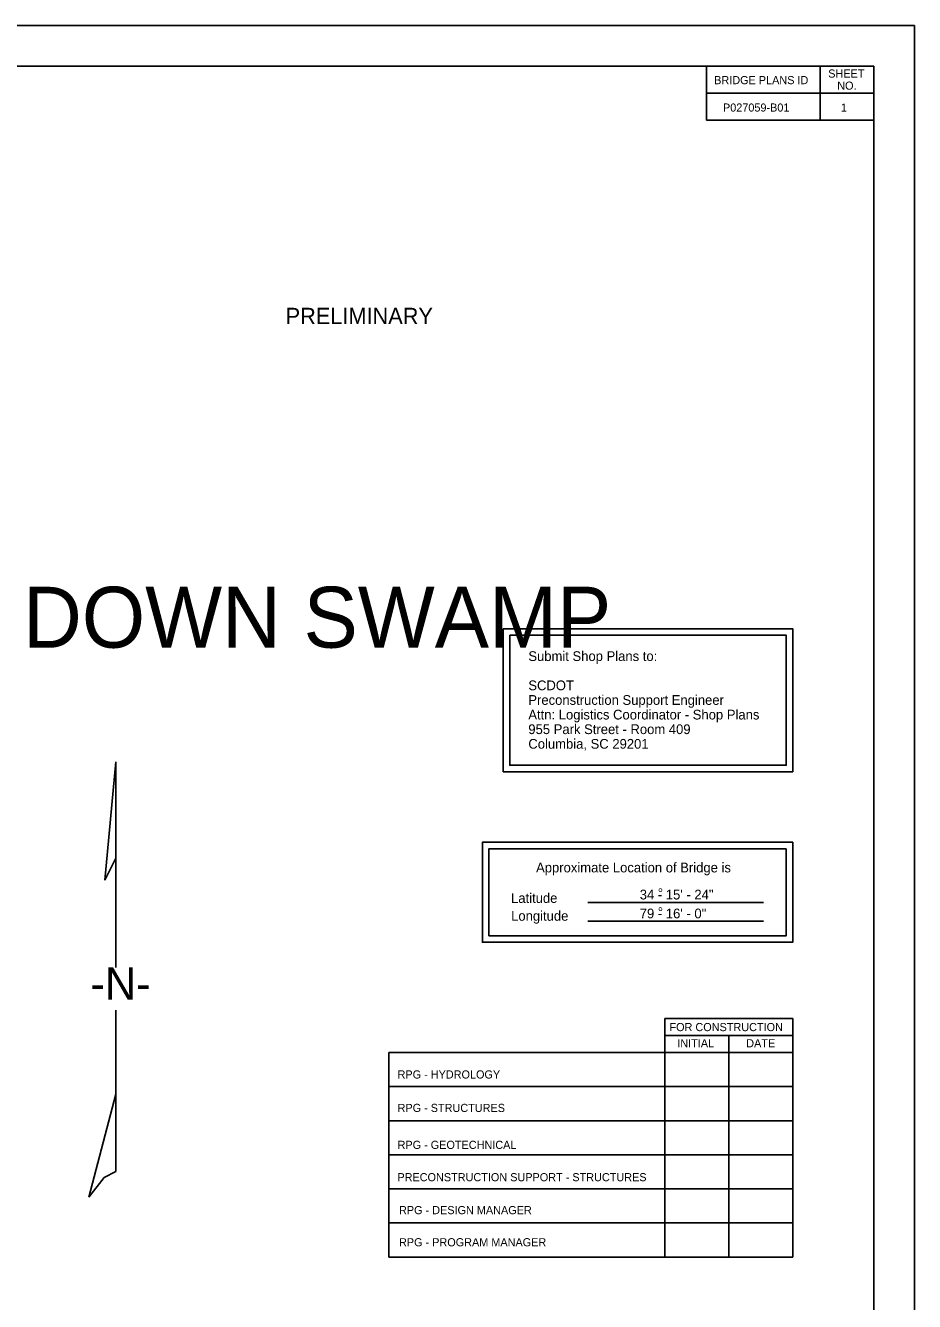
# Model space of a CAD drawing. Extents: x 741 to 2541, y 338 to 1701.
# Drawn here: x 1993 to 2541, y 916 to 1701 of the extents above; entities that cross this region are included whole.
import ezdxf

# ---------------------------------------------------------------- set-up
doc = ezdxf.new("R2010")
doc.units = 0
for name, color, linetype in [('BR_BORDER LINES', 7, 'Continuous'), ('BR_DETAILS', 7, 'Continuous'), ('BR_TEXT', 7, 'Continuous'), ('Default', 7, 'Continuous'), ('RD_SHT_IplotShp', 7, 'Continuous')]:
    doc.layers.add(name, color=color, linetype=linetype)

msp = doc.modelspace()

# ---------------------------------------------------------------- linework, layer by layer
at = {"layer": 'BR_BORDER LINES'}
for p, q in [((740.66, 1701.27), (2540.66, 1701.27)), ((840.66, 1676.27), (2515.66, 1676.27)), ((2412.66, 1642.93), (2412.66, 1676.27)), ((2482.66, 1642.93), (2482.66, 1676.27)), ((2515.66, 626.27), (2515.66, 1676.27)), ((2412.66, 1659.6), (2515.66, 1659.6)), ((2412.66, 1642.93), (2515.66, 1642.93)), ((2515.66, 1618), (2515.66, 1642.87)), ((2515.66, 1265.54), (2515.66, 1618))]:
    msp.add_line(p, q, dxfattribs=at)
at = {"layer": 'Default'}
for p, q in [((2042.19, 1175.06), (2048.86, 1247.85)), ((2048.86, 1247.85), (2048.86, 1188.58)), ((2048.86, 1188.58), (2042.19, 1175.06)), ((2048.86, 1188.58), (2048.86, 1147.48)), ((2339.55, 1161.42), (2447.69, 1161.42)), ((2048.86, 1147.48), (2048.86, 1121.28)), ((2339.55, 1149.84), (2447.69, 1149.84)), ((2048.86, 1095.13), (2048.86, 1043.33)), ((2386.96, 1090), (2465.66, 1090)), ((2386.96, 943), (2386.96, 1090)), ((2465.66, 1090), (2465.66, 943)), ((2386.96, 1079.5), (2465.66, 1079.5)), ((2426.31, 1079.5), (2426.31, 943)), ((2217.01, 1069), (2465.66, 1069)), ((2217.01, 943), (2217.01, 1069)), ((2217.01, 1048), (2465.66, 1048)), ((2032.36, 979.85), (2048.86, 1043.33)), ((2048.86, 1043.33), (2048.86, 1035.48)), ((2048.86, 1035.48), (2048.86, 995.79)), ((2217.01, 1027), (2465.66, 1027)), ((2217.01, 1006), (2465.66, 1006)), ((2217.01, 985), (2465.66, 985)), ((2217.01, 964), (2465.66, 964)), ((2217.01, 943), (2465.66, 943)), ((2217.01, 943), (2459.46, 943))]:
    msp.add_line(p, q, dxfattribs=at)
for points in [[(2287.44, 1329.91), (2465.66, 1329.91), (2465.66, 1241.87), (2287.44, 1241.87)], [(2291.44, 1325.91), (2461.66, 1325.91), (2461.66, 1245.87), (2291.44, 1245.87)], [(2465.69, 1198.43), (2274.63, 1198.43), (2274.63, 1136.84), (2465.69, 1136.84)], [(2461.69, 1194.43), (2278.63, 1194.43), (2278.63, 1140.84), (2461.69, 1140.84)]]:
    msp.add_lwpolyline(points, close=True, dxfattribs=at)
msp.add_lwpolyline([(2048.86, 995.79), (2041.77, 991.91), (2032.36, 979.85)], dxfattribs=at)
at = {"layer": 'RD_SHT_IplotShp'}
msp.add_lwpolyline([(740.66, 1701.2), (2540.66, 1701.2), (2540.66, 601.2), (740.66, 601.2)], close=True, dxfattribs=at)

# ---------------------------------------------------------------- texts
at = {"layer": 'BR_DETAILS'}
for s, height, p in [('SHEET', 5, (2487.55, 1669.2)), ('BRIDGE PLANS ID', 5.0001, (2417.34, 1665.15)), ('NO.', 5, (2493.09, 1661.76))]:
    msp.add_text(s, height=height, dxfattribs=at).set_placement(p)
at = {"layer": 'BR_TEXT'}
for s, p in [('P027059-B01', (2422.76, 1648.27)), ('1', (2495.34, 1648.25))]:
    msp.add_text(s, height=5, dxfattribs=at).set_placement(p)
at = {"layer": 'Default'}
for s, height, p in [('PRELIMINARY', 10, (2153.51, 1517.47)), ('REPLACE BRIDGE OVER MAIDENDOWN SWAMP', 37.5, (1186.5, 1318.22)), ('Submit Shop Plans to:', 6, (2302.91, 1310.01)), ('SCDOT', 6, (2302.91, 1292.01)), ('Preconstruction Support Engineer', 6, (2302.91, 1283.01)), ('Attn: Logistics Coordinator - Shop Plans', 6, (2302.91, 1274.01)), ('955 Park Street - Room 409', 6, (2302.91, 1265.01)), ('Columbia, SC 29201', 6, (2302.91, 1256.01)), ('Approximate Location of Bridge is', 6, (2307.68, 1179.86)), ('Latitude', 6, (2292.27, 1161.06)), ('34 - 15\' - 24"', 6, (2371.51, 1163.19)), ('%%d', 6, (2382.64, 1164.04)), ('Longitude', 6, (2292.32, 1150.09)), ('79 - 16\' - 0"', 6, (2371.51, 1151.57)), ('%%d', 6, (2382.64, 1152.39)), ('-N-', 20, (2033.29, 1101.41)), ('FOR CONSTRUCTION', 5, (2389.82, 1082.13)), ('INITIAL', 5, (2394.62, 1072.17)), ('DATE', 5, (2437.07, 1072.17)), ('RPG - HYDROLOGY ', 5, (2222.41, 1052.96)), ('RPG - STRUCTURES', 5, (2222.41, 1032.36)), ('RPG - GEOTECHNICAL', 5, (2222.41, 1009.62)), ('PRECONSTRUCTION SUPPORT - STRUCTURES', 5, (2222.29, 989.7)), ('RPG - DESIGN MANAGER', 5, (2223.3, 969.43)), ('RPG - PROGRAM MANAGER', 5, (2223.3, 949.64))]:
    msp.add_text(s, height=height, dxfattribs=at).set_placement(p)

doc.saveas('drawing.dxf')
